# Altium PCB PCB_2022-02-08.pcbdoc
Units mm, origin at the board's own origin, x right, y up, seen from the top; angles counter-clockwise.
Board outline 117.85 x 41.75 mm, 2 copper layers (Top Layer, Bottom Layer); 45 components, 36 nets, 193 pads, 214 vias.
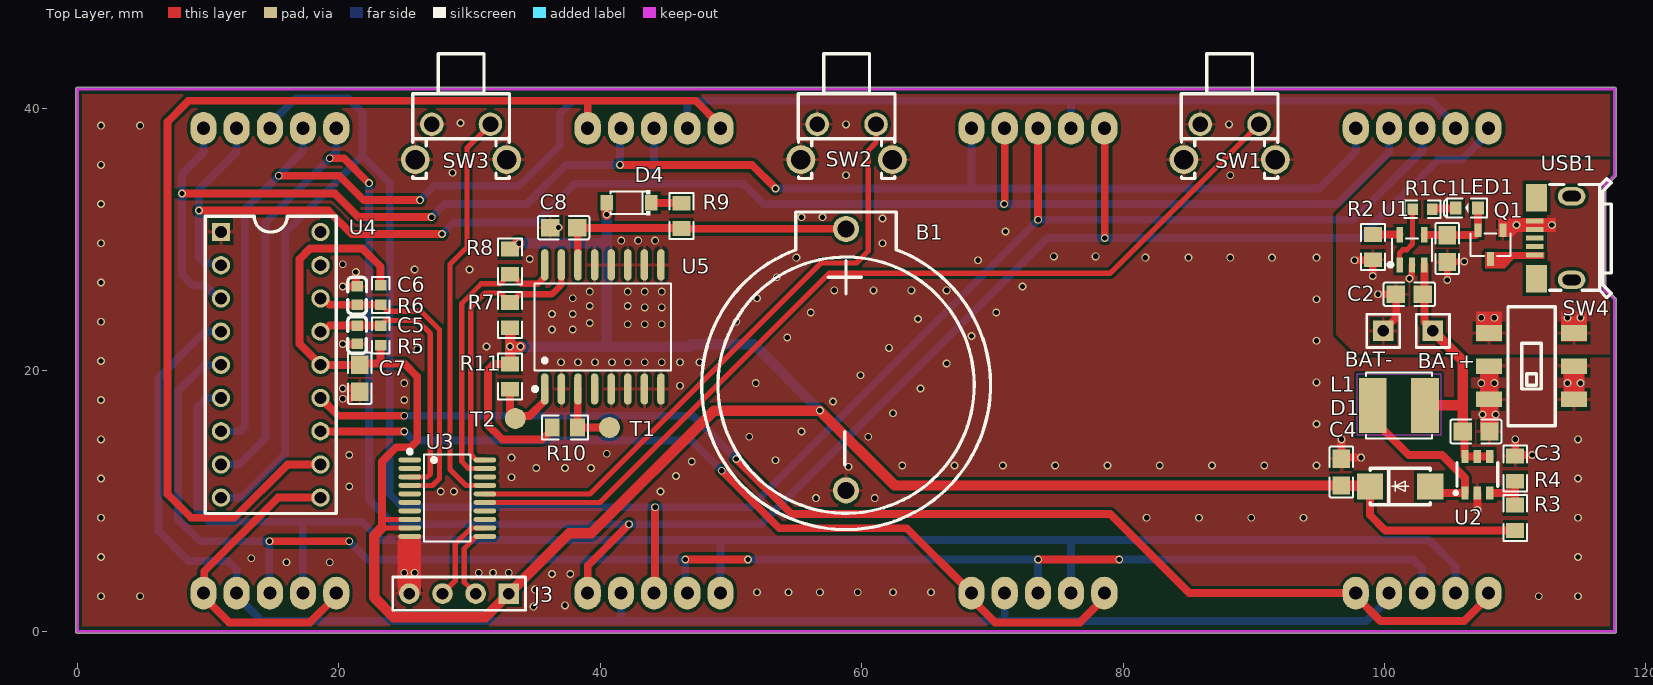
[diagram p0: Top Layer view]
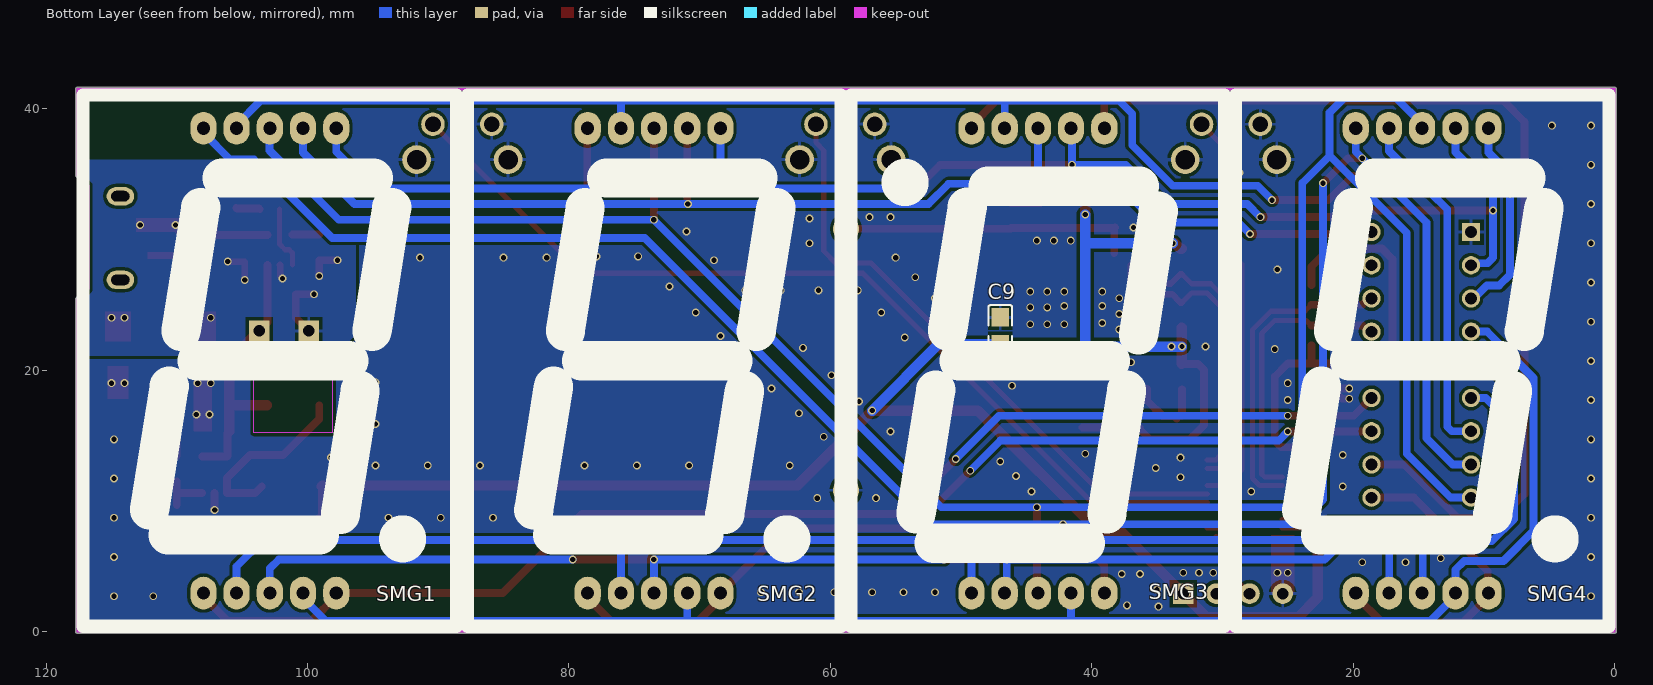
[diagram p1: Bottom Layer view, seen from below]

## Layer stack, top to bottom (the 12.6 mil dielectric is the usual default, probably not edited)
Top Solder: solder mask 0.0102, Solder Resist, Dk 3.5
Top Layer: signal copper 0.0356
Dielectric1: dielectric 0.32, FR-4, Dk 4.8
Bottom Layer: signal copper 0.0356
Bottom Solder: solder mask 0.0102, Solder Resist, Dk 3.5

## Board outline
-0.127,0 -0.127,41.5 cw(c0,41.5) 0,41.627 117.6,41.627 cw(c117.6,41.5) 117.727,41.5 117.727,34.9 cw(c117.6,34.9) 117.69,34.81 116.927,34.047 116.927,26.253 117.69,25.49 cw(c117.6,25.4) 117.727,25.4 117.727,0 cw(c117.6,0) 117.6,-0.127 0,-0.127 cw(c0,0)

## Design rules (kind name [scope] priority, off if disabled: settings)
AssemblyTestPointUsage [All] p1 off:
AssemblyTestpoint [All] p1 off: testpointundercomponent=TRUE minsize=1.016 maxsize=2.54 preferedsize=1.524 minholesize=0 maxholesize=1.016 preferedholesize=0.813 testpointgrid=0.025 usegrid=TRUE gridtolerance=0 allowsidetop=TRUE allowsidebottom=TRUE
Clearance [All] p1: gap=0.25 ignorepadtopadclearanceinfootprint=FALSE
ComponentClearance [All] p1 off: gap=0.254 collisioncheckmode=3 verticalgap=0.254 showdistances=FALSE
DiffPairsRouting [All] p1 off: maxlimit=0.254 minlimit=0.254 mostfreqgap=0.254 toplayer_minwidth=0.381 toplayer_maxwidth=0.381 toplayer_prefwidth=0.381 bottomlayer_minwidth=0.381 bottomlayer_maxwidth=0.381 bottomlayer_prefwidth=0.381 maxuncoupledlength=12.7
FabricationTestPointUsage [All] p1 off: valid=0 allowmultiple=FALSE
FabricationTestpoint [All] p1 off: side=3 testpointundercomponent=TRUE minsize=1.016 maxsize=2.54 preferedsize=1.524 minholesize=0 maxholesize=1.016 preferedholesize=0.813 testpointgrid=0.025 allowsidetop=TRUE allowsidebottom=TRUE usegrid=TRUE gridtolerance=0
FanoutControl Fanout_BGA [IsBGA] p1 off: bgadir=Out bgaviamode=Centered fanoutstyle=Auto fanoutdirection=Alternating viagrid=0.025 // Fanout_BGA (Default Rule)
FanoutControl Fanout_LCC [IsLCC] p2 off: bgadir=Out bgaviamode=Centered fanoutstyle=Auto fanoutdirection=Alternating viagrid=0.025 // Fanout_LCC (Default Rule)
FanoutControl Fanout_SOIC [IsSOIC] p3 off: bgadir=Out bgaviamode=Centered fanoutstyle=Auto fanoutdirection=Alternating viagrid=0.025 // Fanout_SOIC (Default Rule)
FanoutControl Fanout_Small [(CompPinCount < 5)] p4 off: bgadir=Out bgaviamode=Centered fanoutstyle=Auto fanoutdirection=OutThenIn viagrid=0.025 // Fanout_Small (Default Rule)
FanoutControl Fanout_Default [All] p5 off: bgadir=Out bgaviamode=Centered fanoutstyle=Auto fanoutdirection=Alternating viagrid=0.025 // Fanout_Default (Default Rule)
Height [All] p1 off: minheight=0 maxheight=25.4 prefheight=12.7
HoleSize [All] p1 off: absolutevalues=TRUE maxlimit=2.54 minlimit=0.025 maxpercent=80.000 minpercent=20.000
HoleToHoleClearance [All] p1 off: gap=0.254 allowstackedmicrovias=TRUE
LayerPairs [All] p1 off: enforce=TRUE
MinimumSolderMaskSliver [All] p1 off: minsoldermaskwidth=0.254
NetAntennae [All] p1 off: netantennaetolerance=0
PasteMaskExpansion [All] p1 off: expansion=0
PlaneClearance [All] p1 off: clearance=0.508
PlaneConnect [All] p1 off: planeconnectstyle=Relief reliefexpansion=0.508 reliefentries=4 reliefconductorwidth=0.254 reliefairgap=0.254
PolygonConnect [All] p1: thpad.connectstyle=Relief thpad.reliefconductorwidth=0.254 thpad.reliefentries=4 thpad.polygonreliefangle="90 Angle" thpad.airgapwidth=0.254 smdpad.connectstyle=Relief smdpad.reliefconductorwidth=0.254 smdpad.reliefentries=4 smdpad.polygonreliefangle="90 Angle" smdpad.airgapwidth=0.254 via.connectstyle=Direct via.reliefconductorwidth=0.254 via.reliefentries=4 via.polygonreliefangle="90 Angle" via.airgapwidth=0.254
RoutingCorners [All] p1 off: cornerstyle=45-Degree minsetback=2.54 maxsetback=2.54
RoutingLayers [All] p1 off: top layer_v5=TRUE bottom layer_v5=TRUE
RoutingPriority [All] p1 off: routingpriority=0
RoutingTopology [All] p1 off: topology=Shortest
RoutingVias [All] p1: holewidth=0.4 width=0.6 viastyle="Through Hole" minholewidth=0.4 minwidth=0.6 maxholewidth=0.4 maxwidth=0.6
ShortCircuit [All] p1 off: allowed=FALSE
SilkToSilkClearance [All] p1 off: silktosilkclearance=0.254
SilkToSolderMaskClearance [IsPad] p1 off: minsilkscreentomaskgap=0.254 clearancetoexposedcopper=TRUE
SolderMaskExpansion [All] p1 off: expansion=0.102 istentingtop=FALSE
UnRoutedNet [All] p1 off:
UnpouredPolygon [All] p1 off:
Width [All] p1: maxlimit=1 minlimit=0.254 preferedwidth=0.6
1 further rules are at their usual default settings.

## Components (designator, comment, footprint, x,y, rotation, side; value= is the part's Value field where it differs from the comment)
B1 "CR2032-BS-2-1" BAT-TH_BS-2-1 58.8,20.8 r180 top
BAT+ "BAT+" HDR-M-2.54_1X1 103.7,23 r0 top (schematic designator J1)
BAT- "BAT-" HDR-M-2.54_1X1 99.9,23 r0 top (schematic designator J2)
C1 "4.7uf" C0805 104.8,29.3 r90 top
C2 "10uf" C0805 101.9,25.8 r0 top
C3 "22uF" C0805 107,15.3 r180 top
C4 "22uF" C0805 96.7,12.2 r270 top
C5 "101" C0603 21.4,22.7 r90 top
C6 "101" C0603 21.4,25.7 r90 top
C7 "104" C0805 21.6,19.37 r90 top
C8 "0.1u" C0805 37.2,30.9 r0 top
C9 "0.1u" C0805 47,23 r90 bottom
D1 "SS34" DO-214AC_L4.3-W2.7-LS5.3-RD 101.2,11.1 r0 top
D4 "1N4148W-T4" SOD-123_L2.8-W1.8-LS3.7-RD 42.2,32.8 r180 top
J3 "HDR-M-2.54_1x4" HDR-M-2.54_1X4 29.2,2.9 r180 top
L1 "10uH" IND-SMD_L5.0-W5.0 101.1,17.3 r180 top
LED1 "LED-0603_G" LED0603_GREEN 106.3,32.4 r180 top
Q1 "SI2307" SOT-23-3_L3.0-W1.7-P0.95-LS2.9-BR 108.1,29.6 r90 top
R1 "1k" R0603 102.9,32.3 r0 top
R2 "2k 1%" R0805 99.1,29.4 r90 top
R3 "2k2" R0805 110,8.7 r270 top
R4 "300" R0805 110,12.466 r90 top
R5 "10k" R0603 23.2,22.647 r270 top
R6 "10k" R0603 23.2,25.753 r90 top
R7 "10k" R0805 33.1,24.2 r90 top
R8 "10K" R0805 33.1,28.3 r90 top
R9 "200" R0805 46.2,31.8 r90 top
R10 "10K" R0805 37.3,15.6 r0 top
R11 "10K" R0805 33.1,19.5 r270 top
SMG1 "1.2寸1位" ?#1 102.88,20.72 r180 bottom
SMG2 "1.2寸1位" ?#1 73.48,20.72 r180 bottom
SMG3 "1.2寸1位" ?#1 44.12,20.72 r0 bottom
SMG4 "1.2寸1位" ?#1 14.72,20.72 r180 bottom
SW1 "SET" SW-TH_TC-1102N-C-QL-B 88.15,37.45 r180 top
SW2 "CHANGE" SW-TH_TC-1102N-C-QL-B 58.85,37.45 r180 top
SW3 "MODE" SW-TH_TC-1102N-C-QL-B 29.35,37.45 r180 top
SW4 "SS-3235S-L3" SW-SMD_SS-3235S-L3.00 111.25,20.3 r270 top
T1 "测试点1.2" ?#2 40.7,15.6 r180 top
T2 "测试点1.2" ?#2 33.5,16.3 r180 top
U1 "TP4054_C668215" SOT-23-5_L3.0-W1.7-P0.95-LS2.8-BL 102.1,29.2 r0 top
U2 "SX1308" SOT-23-6_L2.9-W1.6-P0.95-LS2.8-BR 107.1,12 r270 top
U3 "STC8H1K17-36I-TSSOP20" TSSOP-20_L6.5-W4.4-P0.65-LS6.4-BL 28.3,10.2 r270 top
U4 "TM1636" DIP18-2.54-22.8X7.62MM 14.79,20.4 r270 top
U5 "DS3231SN#" SOIC-16_L10.3-W7.5-P1.27-LS10.3-BL 40.2,23.3 r0 top
USB1 "U254-051T-4BH82-S2S" MICRO-USB-SMD_U254-051T-4BH82-S2S 112.9,30.1 r90 top

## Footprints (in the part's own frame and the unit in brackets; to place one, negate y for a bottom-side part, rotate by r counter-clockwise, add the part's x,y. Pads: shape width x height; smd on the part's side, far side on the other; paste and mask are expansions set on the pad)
BAT-TH_BS-2-1 [mm]
  round 2 hole 1.3: 1(0,-10) 2(0,10)
  silkscreen extent -11.05,-11.3 11.04,13
C0603 [mm]
  rect 0.8x0.9 smd: 1(-0.7,0) 2(0.7,0)
  silkscreen extent -1.41,-0.71 1.39,0.72
C0805 [mm]
  rect 1.41x1.35 smd: 1(-1.03,0) 2(1.03,0)
  silkscreen extent -1.96,-0.9 1.96,0.9
DIP18-2.54-22.8X7.62MM [mm]
  rect 1.4x1.4 hole 0.899: 1(-10.16,-3.81)
  round 1.4 hole 0.899: 2(-7.62,-3.81) 3(-5.08,-3.81) 4(-2.54,-3.81) 5(0,-3.81) 6(2.54,-3.81) 7(5.08,-3.81) 8(7.62,-3.81) 9(10.16,-3.81) 10(10.16,3.81) 11(7.62,3.81) 12(5.08,3.81) 13(2.54,3.81) 14(0,3.81) 15(-2.54,3.81) 16(-5.08,3.81) 17(-7.62,3.81) 18(-10.16,3.81)
  silkscreen extent -11.38,-5 11.38,5
DO-214AC_L4.3-W2.7-LS5.3-RD [mm]
  rect 2x2 smd: 1(-2.3,0) 2(2.3,0)
  silkscreen extent -2.3,-1.4 2.3,1.4
HDR-M-2.54_1X1 [mil]
  rect 62x62 hole 35: 1(0,0)
  silkscreen extent -50,-50 50,50
HDR-M-2.54_1X4 [mil]
  rect 62x62 hole 35: 1(-150,0)
  round 62 hole 35: 2(-50,0) 3(50,0) 4(150,0)
  silkscreen extent -200,-50 200,50
IND-SMD_L5.0-W5.0 [mm]
  rect 2.124x4.22 smd: 1(2,0) 2(-2,0)
  silkscreen extent -2.53,-2.53 2.53,2.53
LED0603_GREEN [mm]
  rect 0.9x1 smd: 1(-0.85,0) 2(0.85,0)
  silkscreen extent -1.54,-0.73 1.75,0.73
MICRO-USB-SMD_U254-051T-4BH82-S2S [mm]
  rect 0.4x1.35 smd: 1(-1.3,1.413) 2(-0.65,1.413) 3(0,1.413) 4(0.65,1.413) 5(1.3,1.413)
  rect 2.1x1.6 smd: 6(3.1,1.288) 9(-3.1,1.288)
  oval 1.4x2.1 hole 0.8 slot 1.4 at 90 deg: 7(3.2,-1.412) 8(-3.2,-1.412)
  silkscreen extent -4.55,-4.44 4.55,0.26
R0603 [mm]
  rect 0.806x0.864 smd: 1(-0.753,0) 2(0.753,0)
  silkscreen extent -1.39,-0.66 1.39,0.66
R0805 [mm]
  rect 1.133x1.377 smd: 1(-0.966,0) 2(0.966,0)
  silkscreen extent -1.76,-0.92 1.76,0.92
SOD-123_L2.8-W1.8-LS3.7-RD [mm]
  rect 0.95x1.15 smd: 1(-1.693,0) 2(1.693,0)
  silkscreen extent -1.63,-0.94 1.41,0.94
SOIC-16_L10.3-W7.5-P1.27-LS10.3-BL [mm]
  oval 0.574x2.401 smd: 1(-4.445,-4.75) 2(-3.175,-4.75) 3(-1.905,-4.75) 4(-0.635,-4.75) 5(0.635,-4.75) 6(1.905,-4.75) 7(3.175,-4.75) 8(4.445,-4.75) 9(4.445,4.75) 10(3.175,4.75) 11(1.905,4.75) 12(0.635,4.75) 13(-0.635,4.75) 14(-1.905,4.75) 15(-3.175,4.75) 16(-4.445,4.75)
  silkscreen extent -5.33,-4.9 5.23,3.32
SOT-23-3_L3.0-W1.7-P0.95-LS2.9-BR [mm]
  rect 1.037x0.532 smd: 1(1.101,-0.95) 2(1.101,0.95) 3(-1.101,0)
  silkscreen extent -0.86,-1.53 0.86,1.53
SOT-23-5_L3.0-W1.7-P0.95-LS2.8-BL [mm]
  rect 0.49x1.157 smd: 1(-0.95,-1.154) 2(0,-1.154) 3(0.95,-1.154)
  rect 0.49x1.175 smd: 4(0.95,1.154) 5(-0.95,1.154)
  silkscreen extent -1.8,-1.29 1.53,0.85
SOT-23-6_L2.9-W1.6-P0.95-LS2.8-BR [mm]
  rect 1x0.55 smd: 1(1.4,-0.95) 2(1.4,0) 3(1.4,0.95) 4(-1.4,0.95) 5(-1.4,0) 6(-1.4,-0.95)
  silkscreen extent -0.9,-1.78 1.52,1.55
SW-SMD_SS-3235S-L3.00 [mm]
  rect 1.2x2 smd: 1(-2.54,3.25) 2(0,3.25) 3(2.54,3.25) 4(-2.54,-3.25) 5(0,-3.25) 6(2.54,-3.25)
  silkscreen extent -4.55,-1.8 4.55,1.8
SW-TH_TC-1102N-C-QL-B [mm]
  round 1.8 hole 1.2: 1(-2.25,-1.35) 2(2.25,-1.35)
  round 2.2 hole 1.5: 3(-3.5,1.35) 4(3.5,1.35)
  silkscreen extent -3.7,-6.75 3.7,2.79
TSSOP-20_L6.5-W4.4-P0.65-LS6.4-BL [mm]
  oval 0.364x1.742 smd: 1(-2.925,-2.871) 2(-2.275,-2.871) 3(-1.625,-2.871) 4(-0.975,-2.871) 5(-0.325,-2.871) 6(0.325,-2.871) 7(0.975,-2.871) 8(1.625,-2.871) 9(2.275,-2.871) 10(2.925,-2.871) 11(2.925,2.871) 12(2.275,2.871) 13(1.625,2.871) 14(0.975,2.871) 15(0.325,2.871) 16(-0.325,2.871) 17(-0.975,2.871) 18(-1.625,2.871) 19(-2.275,2.871) 20(-2.925,2.871)
  silkscreen extent -3.71,-3.02 3.33,1.77
?#1 [mm]
  oval 2x2.5 hole 1: 1(-5.08,-17.78) 2(-2.54,-17.78) 3(0,-17.78) 4(2.54,-17.78) 5(5.08,-17.78) 6(5.08,17.78) 7(2.54,17.78) 8(0,17.78) 9(-2.54,17.78) 10(-5.08,17.78)
  silkscreen extent -14.29,-20.32 14.29,20.32
?#2 [mm]
  round 1.6 smd: 1(0,0)

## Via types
v1: diameter 0.6, hole 0.4, Top Layer to Bottom Layer, tented both sides, 211 vias
v2: diameter 0.6, hole 0.4, Top Layer to Bottom Layer, 3 vias

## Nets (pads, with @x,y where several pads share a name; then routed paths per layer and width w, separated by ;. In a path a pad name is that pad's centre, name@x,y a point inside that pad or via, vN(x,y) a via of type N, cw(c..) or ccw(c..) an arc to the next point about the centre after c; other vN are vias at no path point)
+5V: Q1.3 USB1.1
A: SMG1.7 SMG2.7 SMG3.3 SMG4.7 U4.2 | length 120.5
  Top Layer w0.6: v1(9.3,32.2) 19.2,32.2 21,30.4 v1(27.9,30.4) ; v1(70.9,32.7) 70.94,32.74 SMG2.7
  Bottom Layer w0.6: U4.2 10.827,28.173 9.727,28.173 9.3,28.6 9.3,33.8 12.18,36.68 SMG4.7 ; v1@27.918,30.418 28.8,31.3 35.1,31.3 38.05,34.25 44.1,34.25 50.95,34.25 52.5,32.7 v1(70.9,32.7) 96.4,32.7 100.34,36.64 SMG1.7 ; 44.1,34.3 44.1,38.48 SMG3.3
B: SMG1.6 SMG2.6 SMG3.2 SMG4.6 U4.3 | length 119
  Top Layer w0.6: v1(8,33.5) 19.7,33.5 21.5,31.7 v1(27.1,31.7) ; v1(41.5,35.7) 51.6,35.7 v1(53.4,33.9)
  Bottom Layer w0.6: SMG4.6 9.64,36.64 8,35 8,27.3 8.818,26.482 9.762,26.482 10.764,25.48 U4.3 ; v1(27.1,31.7) 28.1,32.7 34.4,32.7 37.4,35.7 v1(41.5,35.7) 41.5,38.42 SMG3.2 ; v1(53.4,33.9) 68.4,33.9 ; SMG2.6 68.4,33.9 ; SMG1.6 97.8,36.7 95,33.9 68.4,33.9
BAT+: BAT+.1 C2.2 C3.2 L1.2 U1.3 U2.4 U2.5 U2.6 | length 20.7
  Top Layer w0.6: U1.3 103.046,28.042 103.046,23.654 BAT+.1 ; C3.2 106.125,15.145 106.125,13.425 U2.6 U2.5 U2.4
  Top Layer w0.8: L1.2 105.87,17.3 105.97,17.2 ; BAT+.1 105.97,20.73 105.97,17.2 ; C3.2 105.97,17.2
BGND: BAT-.1 C1.1 C2.1 Q1.1 R2.1 SW4.1 SW4.4 U1.2 USB1.4 USB1.5 | length 11
  Top Layer w0.5: v1(101.9,27) 101.9,27.027 102.095,27.222 102.095,28.041 U1.2 ; v1(104.8,26.9) C1.1 104.815,28.285 106.085,28.285 v1(106.1,28.3)
  Top Layer w0.6: v1(97.7,28.4) 99.066,28.4 99.1,28.366 v1(99.1,27.2) ; v1(99.5,25.8) C2.1 100.9,25.77 100.9,24 BAT-.1
  other v1: 107.4,24 108.4,24 114,24 115,24 110.1,31.1 112.8,31.1
C: SMG1.4 SMG2.4 SMG3.9 SMG4.4 U4.4 | length 121.3
  Bottom Layer w0.6: U4.4 9.74,22.94 6.2,19.4 6.2,7.7 8.5,5.4 11.5,5.4 12.18,4.72 SMG4.4 12.18,2.72 14.1,0.8 98.6,0.8 100.34,2.54 SMG1.4 ; SMG3.9 41.58,0.92 41.6,0.9 ; 70.94,0.96 SMG2.4
D: SMG1.3 SMG2.3 SMG3.7 SMG4.3 U4.5 | length 121.7
  Top Layer w0.6: v1(14.7,6.9) v1(20.8,6.9) ; v1(46.5,5.5) v1(51.3,5.5) ; v1(73.5,5.5) v1(79.7,5.5)
  Bottom Layer w0.6: U4.5 9.7,20.4 7.7,18.4 7.7,8.6 9.4,6.9 v1(14.7,6.9) 14.672,6.872 14.672,2.989 SMG4.3 ; v1(20.8,6.9) 22.2,5.5 v1(46.5,5.5) 46.5,3.1 SMG3.7 ; v1(51.3,5.5) v1(73.5,5.5) 73.5,2.96 SMG2.3 ; v1(79.7,5.5) 102.2,5.5 102.88,4.82 SMG1.3
DP: SMG1.8 SMG2.8 SMG3.8 SMG4.8 U4.9 | length 176.2
  Top Layer w0.6: SMG3.8@44.2,3 v1(44.2,9.5) ; SMG2.8 73.48,31.52 v1(73.5,31.5)
  Bottom Layer w0.6: U4.9 12.54,10.24 15.9,13.6 15.9,30.5 21.8,36.4 ; SMG4.8 14.72,38.82 16.7,40.8 20.7,40.8 21.8,39.7 21.8,36.4 ; SMG1.8@102.9,38.5 102.9,36.8 97.6,31.5 v1(73.5,31.5) v1(73.5,31.5) 51.502,9.5 v1(44.2,9.5) 24.9,9.5 23.9,10.5 23.9,34.3 21.8,36.4
E: SMG1.2 SMG2.2 SMG3.6 SMG4.2 U4.6 | length 123.6
  Bottom Layer w0.6: U4.6 9.86,17.86 9.2,17.2 9.2,9.3 10.1,8.4 17.242,8.4 ; SMG4.2 17.242,2.959 17.242,8.4 ; SMG3.6 49.2,7 ; SMG2.2 76.02,7 ; SMG1.2 105.42,4.98 103.4,7 76.02,7 ; 17.242,8.4 21.8,8.4 23.2,7 49.2,7 ; 49.2,7 76.02,7
F: SMG1.9 SMG2.9 SMG3.4 SMG4.9 U4.7 | length 127.3
  Top Layer w0.6: v1(15.4,34.867) 20.033,34.867 21.9,33 v1(26.2,33)
  Bottom Layer w0.6: U4.7 12.449,15.32 12.8,15.671 12.8,32.3 14.083,33.583 14.117,33.583 v1(15.4,34.867) 15.4,34.9 17.26,36.76 SMG4.9 ; v1(26.2,33) 27.3,34.1 33.8,34.1 36.9,37.2 36.9,39.6 37.9,40.6 46.66,40.6 ; SMG3.4 46.66,40.6 ; SMG2.9 76.02,40.52 76.1,40.6 ; SMG1.9 105.42,38.78 103.6,40.6 76.1,40.6 ; 46.66,40.6 76.1,40.6
G: SMG1.10 SMG2.10 SMG3.10 SMG4.10 U4.8 | length 172.4
  Top Layer w0.6: v1(19.3,36.2) 20.4,36.2 v1(22.3,34.3) ; SMG3.10 39.04,5.04 v1(42.2,8.2) ; SMG2.10 78.6,38.46 v1(78.6,30.1)
  Bottom Layer w0.6: U4.8 12.38,12.78 14.4,14.8 14.4,31.3 v1(19.3,36.2) 19.8,36.7 SMG4.10 ; v1(22.3,34.3) 22.3,10.1 24.2,8.2 v1(42.2,8.2) 52.3,8.2 74.2,30.1 v1(78.6,30.1) 98.1,30.1 104.1,36.1 105.9,36.1 107.96,38.16 SMG1.10
G1: SMG1.1 SMG1.5 U4.13 | length 97.6
  Top Layer w0.6: U4.13 19.96,16.5 v1(25,16.5) ; v1(50.4,13.2) 54.6,9 79,9 85.06,2.94 SMG1.5 97.8,2.69 99.69,0.8 106.1,0.8 107.96,2.66 SMG1.1
  Bottom Layer w0.6: v1(25,16.5) 47.1,16.5 v1(50.4,13.2)
G2: SMG2.1 SMG2.5 U4.12 | length 67.4
  Top Layer w0.6: U4.12 18.62,15.3 v1(25,15.3) ; v1(49.3,12.3) 53.7,7.9 63.44,7.9 SMG2.5 68.4,2.5 70.2,0.7 76.7,0.7 78.56,2.56 SMG2.1
  Bottom Layer w0.6: v1(25,15.3) 25.7,14.6 47,14.6 v1(49.3,12.3)
G3: SMG3.1 SMG3.5 U4.11 | length 88.7
  Top Layer w0.6: U4.11 16.08,12.78 12,8.7 8.7,8.7 6.9,10.5 6.9,39 8.5,40.6 39,40.6 ; SMG3.1 39.04,40.56 39,40.6 ; SMG3.5 49.2,38.7 47.3,40.6 39,40.6
G4: SMG4.1 SMG4.5 U4.10 | length 25.2
  Top Layer w0.6: U4.10 15.34,10.24 9.709,4.609 9.709,3.008 SMG4.5 9.64,2.66 11.6,0.7 17.8,0.7 19.8,2.7 SMG4.1
GND: B1.2 C3.1 C4.1 C5.1 C6.2 C7.1 C8.1 C9.2 J3.4 R4.2 SW1.2 SW1.3 SW1.4 SW2.2 SW2.3 SW2.4 SW3.2 SW3.3 SW3.4 SW4.2 SW4.3 SW4.5 SW4.6 U2.2 U3.10 U4.1 U5.2 U5.5 U5.6 U5.7 U5.8 U5.9 U5.10 U5.11 U5.12 U5.13 | length 13.3
  Top Layer w0.6: v1(20.3,17.8) 20.874,17.8 21.009,17.935 21.225,17.935 21.6,18.31 C7.1 21.34,18.6 v1(20.3,18.6) ; v1(20.3,22) C5.1@21.4,22 ; v1(20.3,26.4) 21.4,26.4 21.3,26.5 v1(21.3,27.5) ; SW3.3@32.85,35.94 SW3.3 ; v1(96.7,14.7) C4.1 96.77,13.3 v1(98.2,13.3) ; v1(107.1,9.3) U2.2 ; v1(110,14.7) R4.2 110.067,13.5 v1(111.3,13.5)
  other v1: 34.9,1.9 37.3,2 1.8,2.7 4.8,2.7 111.8,2.7 114.8,2.7 52,3 54.4,3 56.8,3 59.7,3 62.4,3 65.3,3 35,3.2 36.3,4.4 37.7,4.4 25,4.5 25.8,4.5 30.7,4.5 31.8,4.5 33,4.5 16,5.3 19.3,5.3 13.3,5.6 1.8,5.7 114.8,5.7 1.8,8.7 81.8,8.7 85.8,8.7 89.8,8.7 93.8,8.7 114.8,8.7 56.5,10.2 61,10.2 27.8,10.7 28.8,10.7 44.6,10.7 20.8,11.1 1.8,11.7 114.8,11.7 33.2,11.8 45.8,11.9 35.1,12.5 37.3,12.5 39.3,12.5 59,12.6 63.1,12.7 67.1,12.7 70.8,12.7 74.8,12.7 78.8,12.7 82.8,12.7 86.8,12.7 90.8,12.7 94.8,12.7 47,13 53.4,13.1 33.2,13.3 20.8,13.5 40.5,13.6 1.8,14.7 114.8,14.7 51.4,14.9 60.5,14.9 55.4,15.3 94.8,15.88 107.5,16.6 108.5,16.6 62.4,16.7 57.8,17.6 1.8,17.7 25,17.7 64.5,18.6 46.1,18.8 25,19 51.9,19 107.4,19 108.4,19 114,19 115,19 94.8,19.06 59.9,19.6 66.5,20.5 37,20.6 38.3,20.6 39.6,20.6 40.9,20.6 42.1,20.6 43.4,20.6 44.7,20.6 46.1,20.6 47.6,20.6 1.8,20.7 26,21.6 62.1,21.7 31.3,21.8 94.8,22.24 54.3,22.5 68.4,22.6 36.3,23.1 37.9,23.1 42.1,23.5 43.4,23.5 44.7,23.5 39.2,23.6 1.8,23.7 50.4,23.7 64.3,23.9 36.3,24.3 37.9,24.3 56.1,24.4 70.3,24.4 43.4,24.8 44.7,24.8 39.2,24.9 42.1,24.9 94.8,25.42 37.9,25.5 52,25.5 39.2,26 42.1,26 43.4,26 44.7,26 57.9,26.1 60.9,26.1 63.8,26.1 66.5,26.1 72.3,26.4 1.8,26.7 53.5,27.1 25.8,27.7 30,27.7 20.3,28.1 68.9,28.4 34.6,28.5 55,28.6 81.7,28.6 85,28.6 88.2,28.6 91.4,28.6 94.8,28.6 74.7,28.7 77.9,28.7 1.8,29.7 61.6,29.7 41.6,29.9 42.9,29.9 44.2,29.9 71,30.6 36.8,30.9 61.6,31.6 55.4,31.7 57,31.7 1.8,32.7 58.8,34.9 88.2,34.9 28.7,35.1 1.8,35.7 1.8,38.7 4.8,38.7 58.8,38.8 88.1,38.8 29.3,38.9
K1: SW1.1 U3.15 | length 71.2
  Top Layer w0.4: U3.15 39.975,9.875 57.5,27.4 79,27.4 SW1.1
K2: SW2.1 U3.16 | length 47
  Top Layer w0.4: U3.16 39.225,10.525 56.9,28.2 59.6,28.2 60.5,29.1 60.5,36.8 61.1,37.4 SW2.1
K3: SW3.1 U3.17 | length 30.9
  Top Layer w0.4: U3.17 29.725,11.175 28.5,12.4 28.5,28.1 29.8,29.4 29.8,37 SW3.1
LED1_2: LED1.2 R1.2 | length 1.8
  Top Layer w0.6: R1.2 103.703,32.35 105.4,32.35 LED1.2
R: J3.2 U3.11 | length 5.1
  Top Layer w0.4: J3.2 29.6,3.77 29.6,6.357 U3.11@30.5,7.257
R9_2: D4.1 R9.2 | length 2.3
  Top Layer w0.6: D4.1 43.909,32.783 46.183,32.783 R9.2
RTC_SCL: R8.1 U3.19 U5.16 | length 22.8
  Top Layer w0.4: U3.19 29.925,12.475 29.4,13 29.4,25.1 30.9,26.6 32.366,26.6 R8.1
  Top Layer w0.5: R8.1 33.222,27.334 33.956,26.6 35.218,26.6 35.731,27.113 35.731,28.026 U5.16
RTC_SDA: R7.2 U3.20 U5.15 | length 22.3
  Top Layer w0.4: U3.20 30.518,13.125 30.1,13.543 30.1,24.81 31.19,25.9 32.366,25.9 R7.2
  Top Layer w0.5: R7.2 33.222,25.166 33.539,25.483 33.539,25.507 33.831,25.8 36.3,25.8 37.011,26.511 37.011,28.036 U5.15
SEG_SCL: C6.1 R6.1 U3.4 U4.16 | length 24
  Top Layer w0.4: R6.1 23.7,24.5 26.29,24.5 27.7,23.09 27.7,11.7 27.175,11.175 U3.4
  Top Layer w0.6: U4.16 18.816,25.48 19.296,25 C6.1 R6.1
SEG_SDA: C5.2 R5.1 U3.3 U4.15 | length 21.6
  Top Layer w0.4: R5.1 23.6,23.8 26,23.8 27,22.8 27,12.059 26.766,11.825 U3.3
  Top Layer w0.6: U4.15 18.816,22.94 19.276,23.4 C5.2 R5.1
T: J3.3 U3.12 | length 7
  Top Layer w0.4: J3.3 28.9,3.87 28.9,6.7 30.125,7.925 U3.12
U1_1: R1.1 U1.1 | length 4.8
  Top Layer w0.4: U1.1 101.15,28.95 101.4,29.2 101.7,29.2 102.147,29.647 R1.1
U1_4: C1.2 LED1.1 Q1.2 U1.4 | length 6.1
  Top Layer w0.6: U1.4 103.062,30.342 104.788,30.342 C1.2 106.963,30.33 107.15,30.516 Q1.2 LED1.1
U1_5: R2.2 U1.5 | length 2.1
  Top Layer w0.6: R2.2 99.106,30.36 101.144,30.36 U1.5
U2_1: D1.2 L1.1 U2.1 | length 14
  Top Layer w0.6: L1.1 99.1,16.252 101.852,13.5 104.4,13.5 106.15,11.75 U2.1 104,10.6 D1.2
U2_3: R3.1 R4.1 U2.3 | length 3.8
  Top Layer w0.6: U2.3 109.983,10.6 110,10.583 ; R3.1 110,10.583 ; R4.1 110,10.583
U5_1: R11.2 T2.1 U5.1 | length 5.7
  Top Layer w0.6: T2.1@33.1,16.5 R11.2 ; T2.1 33.691,16.491 34.584,16.491 35.755,17.662 U5.1
U5_3: R10.2 T1.1 U5.3 | length 5.4
  Top Layer w0.6: U5.3 38.282,18.537 38.282,15.616 R10.2 T1.1
U5_14: B1.1 C8.2 R9.1 U5.14 | length 22.6
  Top Layer w0.6: U5.14@38.282,28.951 38.282,30.848 C8.2 38.263,30.867 46.167,30.867 46.217,30.817 58.783,30.817 B1.1
VCC: C4.2 C7.2 C9.1 D1.1 D4.2 J3.1 R3.2 R5.2 R6.2 R7.1 R8.2 R10.1 R11.1 U3.8 U3.9 U4.14 | length 208.6
  Top Layer w0.4: 23.3,7.925 U3.9 ; 23.4,8.575 U3.8
  Top Layer w0.6: 23.2,20.751 R5.2 ; R6.2 23.2,27.9 21.8,29.3 17.8,29.3 17,28.5 17,22 U4.14 C7.2 21.7,20.5 25,20.5 26,19.5 26,14.6 25.5,14.1 24.4,14.1 23.3,13 23.3,8.2 ; R11.1 33.097,20.463 31.863,20.463 31.4,20 31.4,15.8 32.5,14.7 35.556,14.7 36.334,15.478 R10.1 ; D1.1 98.9,8.9 100.066,7.734 R3.2
  Top Layer w0.8: 23.3,7.925 22.7,7.325 22.7,2.6 24.2,1.1 31.21,1.1 J3.1 37.61,7.5 39.3,7.5 48.7,16.9 v2(56.8,16.9) 62.53,11.17 C4.2 96.735,11.135 98.865,11.135 D1.1 ; R11.1 v1(33.1,21.8) ; R7.1 v1(33.1,21.8) ; R8.2 33.222,29.266 33.656,29.7 v2(33.8,29.7) ; v1(33.9,21.8) v1(33.1,21.8) ; v2(40.5,31.9) 40.5,32.793 D4.2
  Bottom Layer w0.8: v1(33.1,21.8) 40.5,21.8 ; v2(33.8,29.7) 40.4,29.7 40.5,29.6 ; v2(40.5,31.9) 40.5,29.6 ; v2(56.8,16.9) 51.73,21.97 C9.1 46.83,21.8 40.5,21.8 ; 40.5,21.8 40.5,29.6
pads on no net: U3.1 U3.2 U3.5 U3.6 U3.7 U3.13 U3.14 U3.18 U4.17 U4.18 U5.4 USB1.2 USB1.3 USB1.6 USB1.7 USB1.8 USB1.9

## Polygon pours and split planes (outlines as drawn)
GND on Bottom Layer "NONET_L-01_P-001" (solid, remove dead copper, pour order 2): 0,41.5 0,0 117.6,0 117.6,41.5
BGND on Bottom Layer "NONET_L-01_P-001" (solid, remove dead copper, pour order 0): 117.6,36.1 117.6,34.9 116.8,34.1 116.8,26.2 117.6,25.4 117.6,21.1 97.9,21.1 96.3,22.7 96.3,31.9 100.5,36.1
GND on Top Layer "NONET_L-01_P-001" (solid, remove dead copper, pour order 4): 0,41.5 0,0 117.6,0 117.6,41.5
GND on Top Layer "NONET_L-01_P-001" (solid, remove dead copper, pour order 3): 0,41.5
BGND on Top Layer "NONET_L-01_P-001" (solid, remove dead copper, pour order 1): 117.6,36.1 117.6,34.9 116.8,34.1 116.8,26.2 117.6,25.4 117.6,21.2 97.8,21.2 96.3,22.7 96.3,31.9 100.5,36.1

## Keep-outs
Top Layer:
  region: 97.9,19.7 104.3,19.7 104.3,15 97.9,15
  region: 97.3,20.2
Bottom Layer:
  region: 98.1,19.4 98.1,15.2 104.1,15.2 104.1,19.4
Keep-Out Layer:
  lines w0.254: 0,0 0,41.5 117.6,41.5 117.6,34.9 116.8,34.1 116.8,26.2 117.6,25.4 117.6,0 0,0

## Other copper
Top Layer:
  rectangle net GND: 24.5,2.9 26.3,7.4
  rectangle net GND: 113.7,17.8 115.3,20.3
  rectangle net GND: 107.3,15.3 108.7,20.3
  rectangle net BGND: 113.5,22.2 115.5,24.5
  rectangle net BGND: 107,22.2 109,24.5
  region net +5V: 107.7,29 107.7,27.8 109.2,27.8 109.9,28.5 112.2,28.5 112.2,29
  region: 107.8,29.2
  region net BGND: 108.7,31.6 108.7,30.2 109.8,30.2 110.2,30.6 113.1,30.6 113.1,31.6

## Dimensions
117.6,0 to 0,0 on Document
0,41.5 to 0,0 on Document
